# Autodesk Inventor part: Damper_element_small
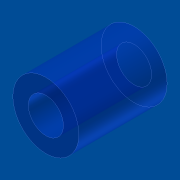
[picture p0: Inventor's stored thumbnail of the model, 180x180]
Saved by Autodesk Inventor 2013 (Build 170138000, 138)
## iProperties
Shininess: 20.0
Length Units: 11269
Angle Units: 11279
Time Units: 11290
Mass Units: 11283
Length Display Precision: 3
Angle Display Precision: 2
Created: 2001-04
Part Number: Damper_element_small
Material: Standard
Document SubType Name: Modellieren
Designer: dl
Density: 1 g/cm^3
Density: 0.0
Volumn: 0.0
Area: 0.0
PropertySet Name: Model Information
Control State: 0
Master: False
Checked Out: False
Author: dl
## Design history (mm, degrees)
body "Solid1"
sketch "Sketch1"
  geometry: C1 r 8 at (0, 0); C2 r 4.25 at (0, 0)
  constraints: 2 centre point, 1 coincident
  dimensions: "d0" = 16 diameter of C1; "d1" = 8.5 diameter of C2
extrude "Extrusion1" new body sketch "Sketch1" distance "d2" = 21.4; taper "d3" = 0 deg
